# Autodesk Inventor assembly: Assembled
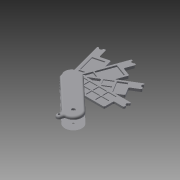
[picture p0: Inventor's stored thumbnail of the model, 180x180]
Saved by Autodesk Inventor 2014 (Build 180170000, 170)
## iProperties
Created: 2015-01
Part Number: Assembled
Document SubType Name: Assembly
Designer: Drano
Author: Drano
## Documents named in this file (7)
- C:\Users\Drano\Documents\SD swiss army\Assembled.iam
- C:\Users\Drano\Documents\SD swiss army\8XMicroSD-assembled.ipt
- C:\Users\Drano\Documents\SD swiss army\1XSD-2XMicroSD-1XRaspiAdaptor-assembled.ipt
- C:\Users\Drano\Documents\SD swiss army\outer side 2.ipt
- C:\Users\Drano\Documents\SD swiss army\outer side 1 with text.ipt
- C:\Users\Drano\Documents\SD swiss army\2XSD-assembled.ipt
- C:\Users\Drano\Documents\SD swiss army\2XMSDuo-assembled.ipt
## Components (6 placed, 6 different names)
1. 8XMicroSD-assembled:1 — Mate:1, Mate:2, Mate:9
2. 1XSD-2XMicroSD-1XRaspiAdaptor-assembled:1 — Mate:2, Mate:3, Mate:8
3. outer side 2:1 — Mate:1, Mate:10, Mate:11
4. outer side 1 with text:1 — Mate:5, Mate:6, Mate:7, Mate:9, Mate:10, Mate:11
5. 2XSD-assembled:1 — Mate:3, Mate:4, Mate:7
6. 2XMSDuo-assembled:1 — Mate:4, Mate:5, Mate:6, Mate:8
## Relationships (11: Mate 11)
- Mate:1: 8XMicroSD-assembled:1 ↔ outer side 2:1
- Mate:2: 8XMicroSD-assembled:1 ↔ 1XSD-2XMicroSD-1XRaspiAdaptor-assembled:1
- Mate:3: 1XSD-2XMicroSD-1XRaspiAdaptor-assembled:1 ↔ 2XSD-assembled:1
- Mate:4: 2XSD-assembled:1 ↔ 2XMSDuo-assembled:1
- Mate:5: outer side 1 with text:1 ↔ 2XMSDuo-assembled:1
- Mate:6: outer side 1 with text:1 ↔ 2XMSDuo-assembled:1
- Mate:7: outer side 1 with text:1 ↔ 2XSD-assembled:1
- Mate:8: 1XSD-2XMicroSD-1XRaspiAdaptor-assembled:1 ↔ 2XMSDuo-assembled:1
- Mate:9: 8XMicroSD-assembled:1 ↔ outer side 1 with text:1
- Mate:10: outer side 2:1 ↔ outer side 1 with text:1
- Mate:11: outer side 2:1 ↔ outer side 1 with text:1
